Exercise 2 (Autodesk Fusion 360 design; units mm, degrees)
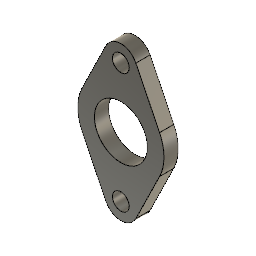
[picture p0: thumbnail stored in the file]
sketch "Sketch1" plane through (0, 0, 0) normal (0, 1, 0) x axis (1, 0, 0)
  line L1 (38.4058, 0) -> (0, 0)
  line L2 (-16.164, -7.92) -> (-6.286, -28.08)
  line L3 (-6.286, 28.08) -> (-16.164, 7.92)
  line L4 (16.164, 7.92) -> (6.286, 28.08)
  line L5 (16.164, -7.92) -> (6.286, -28.08)
  circle C1 centre (0, 0) radius 11
  arc A1 centre (0, -25) radius 7 clockwise from (6.286, -28.08) to (-6.286, -28.08)
  arc A2 centre (0, 0) radius 18 clockwise from (16.164, 7.92) to (16.164, -7.92)
  arc A3 centre (0, 0) radius 18 clockwise from (-16.164, -7.92) to (-16.1621, 7.9238)
  arc A4 centre (0, 25) radius 7 clockwise from (-6.286, 28.08) to (6.286, 28.08)
  circle C2 centre (0, -25) radius 3.5
  circle C3 centre (0, 25) radius 3.5
  point P1 (0, 0)
  point P2 (0, 0)
  point P3 (0, 0)
  point P6 (0, 0)
  point P4 (0, -25)
  point P5 (0, 25)
  point P10 (-16.164, 7.92)
  point P16 (-16.1621, 7.9238)
  coincident P1 P2
  coincident P1 P3
  equal A1 A4
  coincident P1 P6
  horizontal L1
  symmetric P4 P5 L1
  vertical P3 P4
  tangent L2 A2
  coincident P10 A2
  tangent L3 A4
  tangent L4 A2
  tangent L5 A2
  tangent L2 A1
  tangent L5 A1
  tangent L4 A4
  tangent L3 A2
  coincident L3 P16
  concentric A2 A3
  equal A2 A3
  concentric A1 C2
  concentric A4 C3
  equal C2 C3
  dimension "d1" diameter C1 = 22
  dimension "d2" radius A2 = 18
  dimension "d3" distance P4 P5 = 50
  dimension "d4" radius A1 = 7
  dimension "d5" diameter C2 = 7
extrude "Extrude1" new body sketch "Sketch1" profile of C1 A3 A1 A4 L2 L3 L4 L5 C2 C3 along normal blind 6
